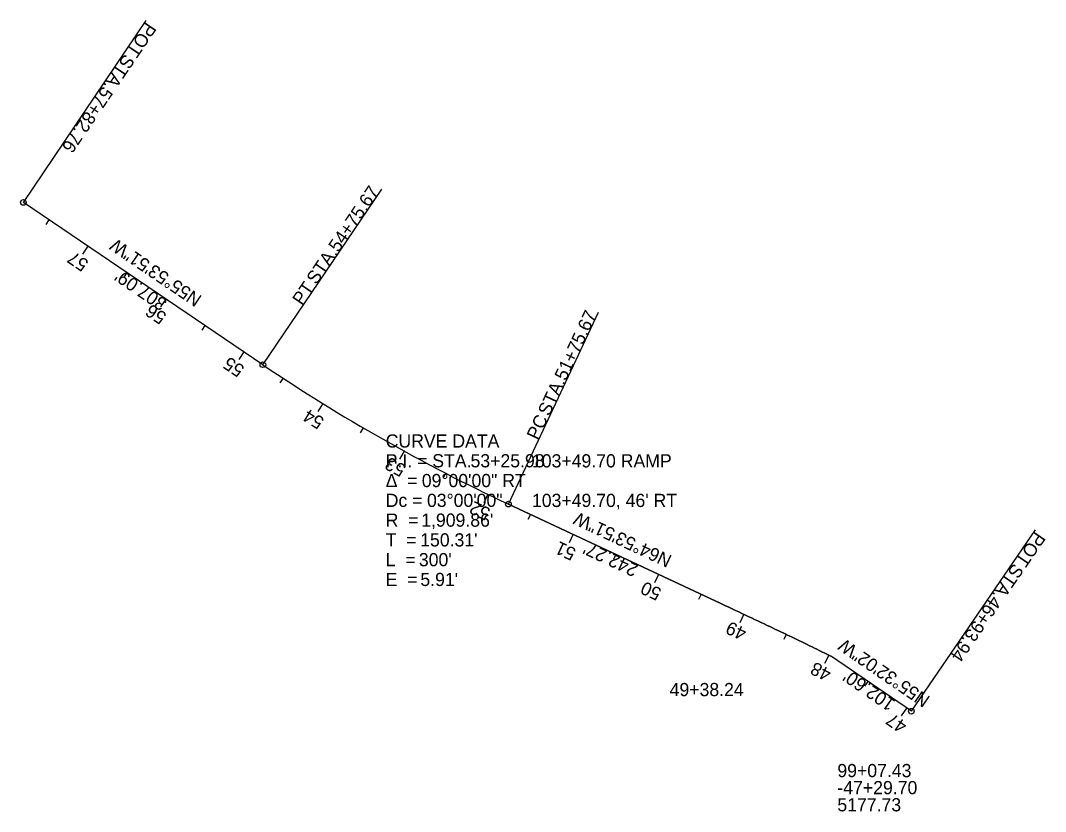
# Model space of a CAD drawing. Extents: x 1699539 to 1700627, y 716855 to 717695.
import ezdxf

# ---------------------------------------------------------------- set-up
doc = ezdxf.new("R2010")
doc.units = 0
for name, color, linetype in [('Default', 7, 'Continuous'), ('DR_X_Cells', 7, 'Continuous'), ('PM_X_Cells', 7, 'Continuous'), ('SC_Scratch1', 7, 'Continuous'), ('SN_X_Public', 7, 'Continuous'), ('SV_X_Break_Lines', 7, 'Continuous'), ('SV_X_Random_Point', 7, 'Continuous'), ('SV_X_Shot_Marker', 7, 'Continuous'), ('UT_X_Unknown_Cells', 7, 'Continuous')]:
    doc.layers.add(name, color=color, linetype=linetype)

msp = doc.modelspace()

# ---------------------------------------------------------------- linework, layer by layer
at = {"layer": 'Default'}
msp.add_open_spline([(1700276.3, 717078.9), (1700291.4, 717071.8), (1700306.5, 717064.7), (1700336.9, 717050.4), (1700352, 717043.2), (1700378.1, 717030.5), (1700388.9, 717025.2), (1700399.8, 717019.8)], degree=3, dxfattribs=at)
at = {"layer": 'DR_X_Cells'}
msp.add_line((1700056.9, 717181.7), (1700276.3, 717078.9), dxfattribs=at)
at = {"layer": 'SN_X_Public'}
for p, q in [((1699542.1, 717501.9), (1699672.4, 717695.1)), ((1699796.3, 717329.7), (1699922.5, 717516)), ((1700056.9, 717181.7), (1700152.4, 717385.4)), ((1700484.4, 716961.8), (1700616, 717154.2))]:
    msp.add_line(p, q, dxfattribs=at)
for centre in [(1699542.1, 717501.9), (1699796.3, 717329.7), (1700056.9, 717181.7), (1700484.4, 716961.8)]:
    msp.add_circle(centre, 3, dxfattribs=at)
at = {"layer": 'SV_X_Random_Point'}
for p, q in [((1699569.2, 717483.5), (1699565.8, 717478.5)), ((1699610.6, 717455.5), (1699605, 717447.2)), ((1699652, 717427.4), (1699648.6, 717422.5)), ((1699693.4, 717399.4), (1699687.8, 717391.1)), ((1699734.8, 717371.4), (1699731.4, 717366.4)), ((1699776.2, 717343.3), (1699770.6, 717335.1)), ((1699817.7, 717315.5), (1699814.4, 717310.4)), ((1699859.8, 717288.5), (1699854.6, 717280)), ((1699902.7, 717262.7), (1699899.6, 717257.5)), ((1699946.1, 717238), (1699941.3, 717229.3)), ((1699990.2, 717214.5), (1699987.5, 717209.2)), ((1700035, 717192.1), (1700030.6, 717183.1)), ((1700080.2, 717170.8), (1700077.6, 717165.3)), ((1700125.4, 717149.6), (1700121.2, 717140.5)), ((1700170.7, 717128.3), (1700168.2, 717122.9)), ((1700216, 717107.1), (1700211.8, 717098.1)), ((1700261.3, 717085.9), (1700258.7, 717080.5)), ((1700306.5, 717064.7), (1700302.3, 717055.6)), ((1700351.7, 717043.3), (1700349.1, 717037.9)), ((1700396.7, 717021.4), (1700392.2, 717012.4)), ((1700438.1, 716993.5), (1700434.7, 716988.5)), ((1700479.4, 716965.2), (1700473.7, 716956.9))]:
    msp.add_line(p, q, dxfattribs=at)
at = {"layer": 'SV_X_Shot_Marker'}
for p, q in [((1699796.3, 717329.7), (1699542.1, 717501.9)), ((1700276.3, 717078.9), (1700056.9, 717181.7)), ((1700484.4, 716961.8), (1700399.8, 717019.8))]:
    msp.add_line(p, q, dxfattribs=at)
msp.add_arc((1700867.2, 718911.1), 1909.9, 235.8975, 244.8975, dxfattribs=at)
msp.add_open_spline([(1700399.8, 717019.8), (1700388.9, 717025.2), (1700378.1, 717030.5), (1700352, 717043.2), (1700336.9, 717050.4), (1700306.5, 717064.7), (1700291.4, 717071.8), (1700276.3, 717078.9)], degree=3, dxfattribs=at)

# ---------------------------------------------------------------- texts
at = {"layer": 'PM_X_Cells'}
for s, rotation, p in [('N55°53\'51"W', 145.8975, (1699732.5, 717401.9)), ('N64°53\'51"W', 154.8975, (1700231.3, 717126.5)), ('N55°32\'02"W', 145.5338, (1700505.2, 716976.5))]:
    msp.add_text(s, height=14, rotation=rotation, dxfattribs=at).set_placement(p)
at = {"layer": 'SC_Scratch1'}
for s, p in [('103+49.70 RAMP', (1700081.8, 717220.6)), ("103+49.70, 46' RT", (1700081.8, 717178.6)), ('49+38.24', (1700227.9, 716977.8)), ('99+07.43', (1700405.9, 716891.8)), ('-47+29.70', (1700405.9, 716873.7)), ('5177.73', (1700405.9, 716855.5))]:
    msp.add_text(s, height=14, dxfattribs=at).set_placement(p)
at = {"layer": 'SN_X_Public'}
for s, rotation, p in [('POT', 235.8975, (1699672.5, 717694.2)), (' STA. ', 235.8975, (1699652.5, 717664.7)), ('57+82.76', 235.8975, (1699626.4, 717626.1)), ('54+75.67', 55.8975, (1699876.4, 717448.2)), (' STA. ', 55.8975, (1699850.2, 717409.6)), ('PT', 55.8975, (1699838.1, 717391.6)), ('51+75.67', 64.8975, (1700117.7, 717311.8)), (' STA. ', 64.8975, (1700097.9, 717269.6)), ('PC', 64.8975, (1700088.2, 717248.8)), ('POT', 235.5338, (1700616.1, 717153.3)), (' STA. ', 235.5338, (1700595.9, 717123.9)), ('46+93.94', 235.5338, (1700569.5, 717085.5))]:
    msp.add_text(s, height=14, rotation=rotation, dxfattribs=at).set_placement(p)
at = {"layer": 'SV_X_Break_Lines'}
for s, rotation, p in [("307.09'", 145.8975, (1699695.8, 717397.6)), ("242.27'", 154.8975, (1700195.7, 717116.5)), ("102.60'", 145.5338, (1700468.5, 716972.4))]:
    msp.add_text(s, height=14, rotation=rotation, dxfattribs=at).set_placement(p)
at = {"layer": 'SV_X_Random_Point'}
for s, rotation, p in [('57', 145.8975, (1699612.4, 717439.2)), ('56', 145.8975, (1699695.2, 717383.1)), ('55', 145.8975, (1699777.8, 717327.1)), ('54', 148.1676, (1699862.4, 717272.2)), ('53', 151.1676, (1699949.2, 717222.1)), ('52', 154.1676, (1700038.9, 717176.3)), ('51', 154.8975, (1700129.7, 717133.8)), ('50', 154.8975, (1700220.4, 717091.3)), ('49', 154.8141, (1700310.8, 717048.9)), ('48', 153.5838, (1700400.7, 717005.4)), ('47', 145.5338, (1700481.1, 716948.9))]:
    msp.add_text(s, height=14, rotation=rotation, dxfattribs=at).set_placement(p)
at = {"layer": 'UT_X_Unknown_Cells'}
for s, p in [('CURVE DATA', (1699926.6, 717241.7)), ('P.I. = STA. ', (1699926.6, 717220.7)), ('53+25.98', (1700016.6, 717220.7)), ('Δ  = ', (1699926.6, 717199.7)), ('09°00\'00" RT', (1699964.9, 717199.7)), ('Dc = ', (1699926.6, 717178.7)), ('03°00\'00"', (1699970.4, 717178.7)), ('R  = ', (1699926.6, 717157.7)), ("1,909.86'", (1699964.3, 717157.7)), ("150.31'", (1699963.2, 717136.7)), ('T  = ', (1699926.6, 717136.7)), ('L  = ', (1699926.6, 717115.7)), ("300'", (1699961.8, 717115.7)), ('E  = ', (1699926.6, 717094.7)), ("5.91'", (1699963.4, 717094.7))]:
    msp.add_text(s, height=14, dxfattribs=at).set_placement(p)

doc.saveas('drawing.dxf')
